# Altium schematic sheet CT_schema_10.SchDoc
size 209 x 185 mm
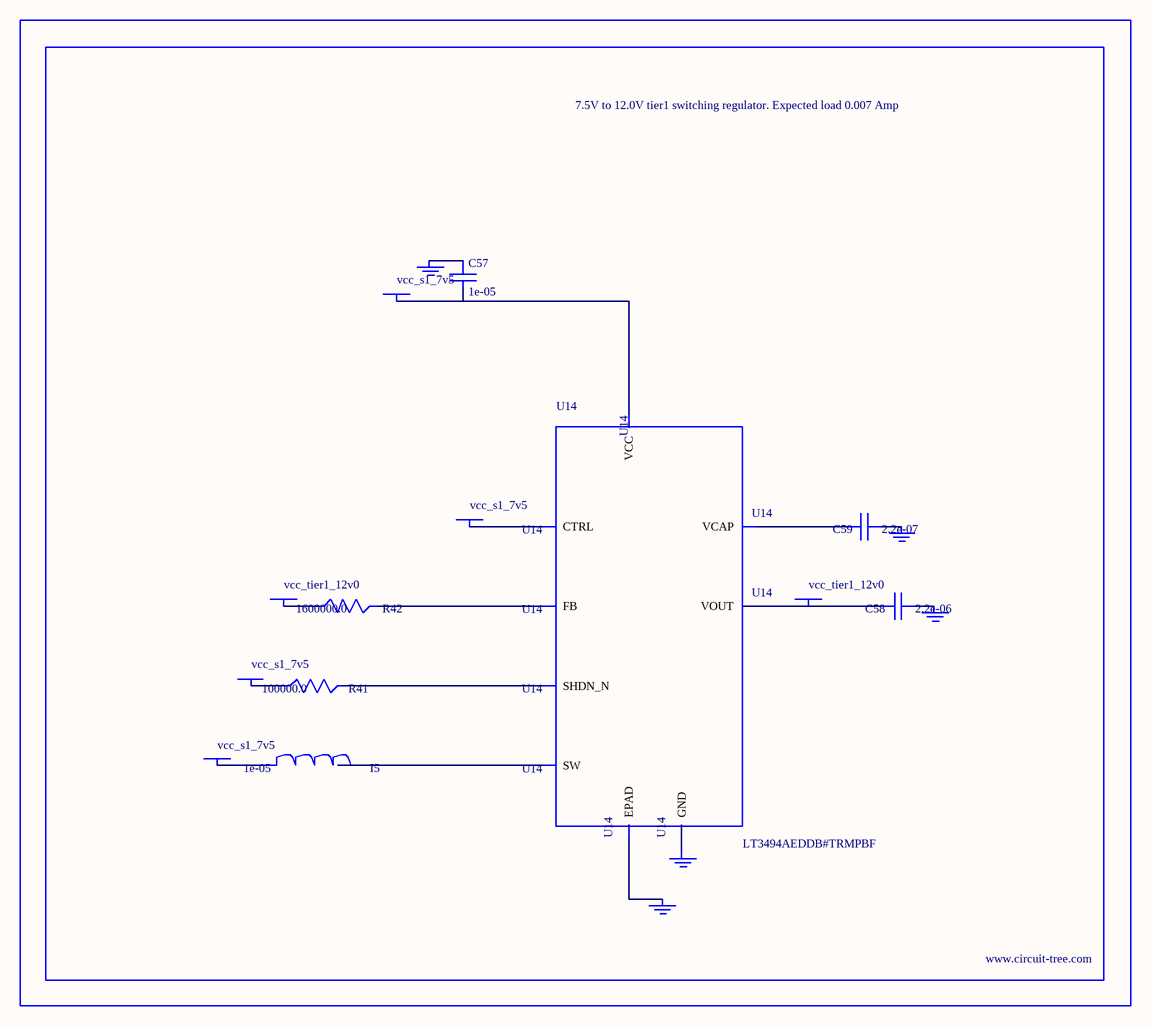
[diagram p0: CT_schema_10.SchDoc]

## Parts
BORDER9  (no value)
C57  1e-05  [C1210]
C58  2.2e-06  [C0603]
C59  2.2e-07  [C0603]
GND_INSTANCE_9_0  (no value)
GND_INSTANCE_9_1  (no value)
GND_INSTANCE_9_2  (no value)
GND_INSTANCE_9_3  (no value)
GND_INSTANCE_9_4  (no value)
I5  1e-05  [L1210]
POWER_INSTANCE_9_0  vcc_s1_7v5
POWER_INSTANCE_9_1  vcc_s1_7v5
POWER_INSTANCE_9_2  vcc_s1_7v5
POWER_INSTANCE_9_3  vcc_s1_7v5
POWER_INSTANCE_9_4  vcc_tier1_12v0
POWER_INSTANCE_9_5  vcc_tier1_12v0
R41  100000.0  [R0603]
R42  1600000.0  [R0603]
U14  LT3494AEDDB#TRMPBF  [DFN-8_DDB]

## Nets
NetC57_1: C57.1 GND_INSTANCE_9_0.0(GND)
NetC57_2: C57.2 POWER_INSTANCE_9_1.0(PWR) U14.3(VCC)
NetC58_1: C58.1 GND_INSTANCE_9_1.0(GND)
NetC58_2: C58.2 POWER_INSTANCE_9_5.0(PWR) U14.7(VOUT)
NetC59_1: C59.1 GND_INSTANCE_9_2.0(GND)
NetC59_2: C59.2 U14.8(VCAP)
NetGND_INSTANCE_9_3_0: GND_INSTANCE_9_3.0(GND) U14.9(EPAD)
NetGND_INSTANCE_9_4_0: GND_INSTANCE_9_4.0(GND) U14.2(GND)
NetI5_1: I5.1 POWER_INSTANCE_9_0.0(PWR)
NetI5_2: I5.2 U14.1(SW)
NetPOWER_INSTANCE_9_2_0: POWER_INSTANCE_9_2.0(PWR) U14.4(CTRL)
NetPOWER_INSTANCE_9_3_0: POWER_INSTANCE_9_3.0(PWR) R41.1
NetPOWER_INSTANCE_9_4_0: POWER_INSTANCE_9_4.0(PWR) R42.1
NetR41_2: R41.2 U14.5(SHDN_N)
NetR42_2: R42.2 U14.6(FB)

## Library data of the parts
BORDER9 = BORDER_PAGE9
C57 = C1210C106K5PACTU
C58 = GRM188R61H225KE1115D
C59 = C0603C224K3RAC
GND_INSTANCE_9_0-GND_INSTANCE_9_4 = GND
I5 = CBC3225T100MR
POWER_INSTANCE_9_0-POWER_INSTANCE_9_5 = PWR
R41 = RC0603JR-07100KL
R42 = RC0603JR-071M6L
